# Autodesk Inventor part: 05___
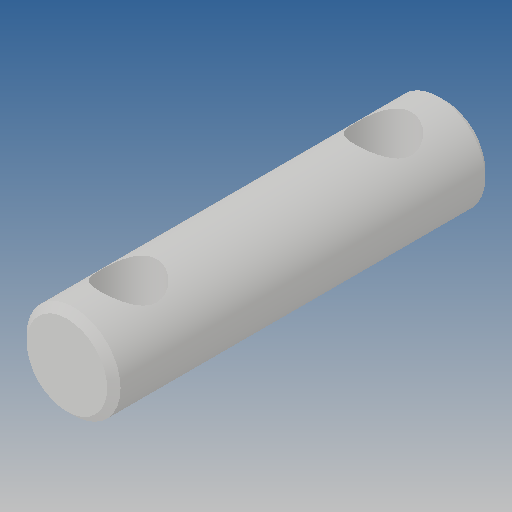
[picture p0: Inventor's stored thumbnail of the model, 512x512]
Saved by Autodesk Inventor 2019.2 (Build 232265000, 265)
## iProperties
Created: 2010-06
Part Number: 05___
Material: Ogólny
Document SubType Name: Modeling
Designer: CADENGINEERING4
Density: 1 g/cm^3
Appearance: Domyślna
Author: CADENGINEERING4
Revision Number: ANY
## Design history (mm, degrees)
feature "NONE"
node "Bryła1"
